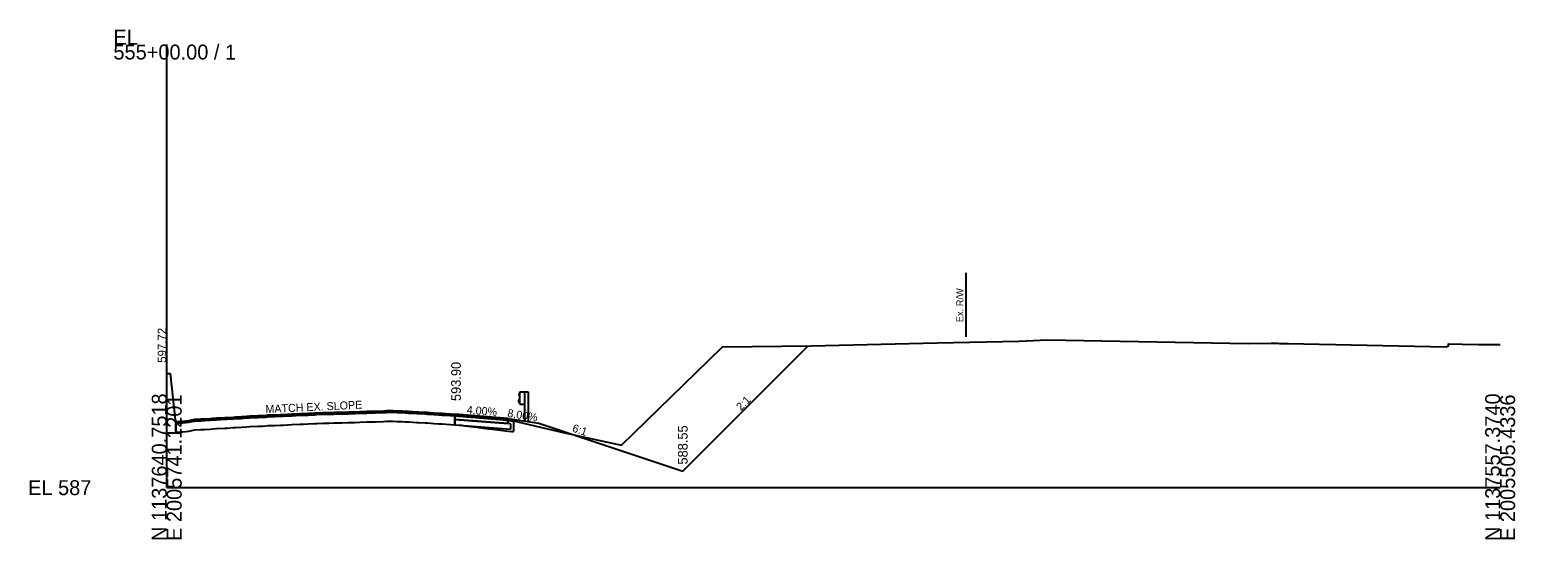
# Model space of a CAD drawing. Extents: x -201 to 2007062, y -213 to 1139737.
# Drawn here: x -25.7 to 252.8, y 8490.3 to 8585.9 of the extents above; entities that cross this region are included whole.
import ezdxf

# ---------------------------------------------------------------- set-up
doc = ezdxf.new("R2010")
doc.units = 0
for name, color, linetype in [('Default', 7, 'Continuous'), ('RD_GPK_XS_Cell', 7, 'Continuous'), ('RD_Sketch1', 7, 'Continuous'), ('RD_XS_Base', 7, 'Continuous'), ('RD_XS_EarthShd', 7, 'Continuous'), ('RD_XS_ExGround', 7, 'Continuous'), ('RD_XS_ExPaveRet', 7, 'Continuous'), ('RD_XS_ExRW', 7, 'Continuous'), ('RD_XS_GR', 7, 'Continuous'), ('RD_XS_PaveOvlay', 7, 'Continuous'), ('RD_XS_PaveShd', 7, 'Continuous'), ('RD_XS_TieSlope', 7, 'Continuous'), ('RD_XS_TX_Ditch', 7, 'Continuous'), ('RD_XS_TX_Elev_EX', 7, 'Continuous'), ('RD_XS_TX_Elev_PR', 7, 'Continuous'), ('RD_XS_TX_Slope', 7, 'Continuous')]:
    doc.layers.add(name, color=color, linetype=linetype)

msp = doc.modelspace()

# ---------------------------------------------------------------- linework, layer by layer
at = {"layer": 'RD_GPK_XS_Cell'}
for q in [(0, 8583.15), (250, 8500)]:
    msp.add_line((0, 8500), q, dxfattribs=at)
at = {"layer": 'RD_XS_Base'}
for points in [[(64, 8512.68), (54, 8513.48)], [(54, 8513.48), (54, 8512.82)], [(64.5, 8511.98), (64, 8512.02), (54, 8512.82)], [(54, 8512.82), (54, 8511.82)], [(54, 8512.82), (64, 8512.02)], [(64, 8512.02), (64, 8512.68)], [(64.5, 8510.98), (64.5, 8511.98)], [(54, 8511.82), (64.5, 8510.98)]]:
    msp.add_lwpolyline(points, dxfattribs=at)
at = {"layer": 'RD_XS_EarthShd'}
msp.add_lwpolyline([(64, 8513.01), (69.75, 8512.09)], dxfattribs=at)
at = {"layer": 'RD_XS_ExGround'}
msp.add_lwpolyline([(0, 8521.44), (0.65, 8521.43), (1.59, 8512.73), (1.68, 8512.41), (2.7, 8512.47), (3.03, 8512.49), (4.14, 8512.62), (4.73, 8512.75), (5.26, 8512.83), (6.41, 8512.89), (7.09, 8512.94), (8.11, 8512.99), (8.61, 8513.03), (9.3, 8513.09), (10.87, 8513.17), (11.25, 8513.19), (12.44, 8513.26), (12.86, 8513.28), (14, 8513.34), (14.98, 8513.41), (15.57, 8513.45), (17.14, 8513.52), (18.02, 8513.56), (18.59, 8513.6), (18.98, 8513.64), (19.83, 8513.66), (20.27, 8513.68), (21.34, 8513.73), (21.84, 8513.75), (23.46, 8513.84), (24.97, 8513.92), (25.58, 8513.94), (26.54, 8513.96), (27.71, 8514.03), (28.11, 8514.04), (29.24, 8514.11), (29.83, 8514.13), (30.4, 8514.11), (31.38, 8514.16), (31.81, 8514.16), (32.4, 8514.18), (32.81, 8514.19), (34.07, 8514.21), (34.38, 8514.22), (35.24, 8514.25), (36.19, 8514.29), (37.51, 8514.33), (38.31, 8514.35), (39.08, 8514.36), (40.64, 8514.41), (41.23, 8514.45), (42.46, 8514.5), (43.2, 8514.44), (43.54, 8514.43), (44.16, 8514.41), (44.68, 8514.38), (45.35, 8514.34), (46.91, 8514.26), (47.23, 8514.24), (48.48, 8514.18), (48.92, 8514.15), (50.05, 8514.06), (51.04, 8514), (51.61, 8513.96), (53.18, 8513.88), (55.29, 8513.7), (55.89, 8513.62), (58.16, 8513.34), (59.04, 8513.21), (59.41, 8513.16), (60.38, 8513.03), (61.02, 8512.99), (61.65, 8512.93), (62.58, 8512.82), (63.99, 8512.61), (64.62, 8512.54), (65, 8512.55), (74.34, 8510.36), (85.24, 8507.96), (101.65, 8523.92), (104.23, 8526.44), (120.84, 8526.63), (144.46, 8527.15), (159.8, 8527.52), (165.09, 8527.72), (202.77, 8527.04), (207.05, 8527.11), (207.55, 8527.1), (208.31, 8527.09), (208.61, 8527.08), (210.31, 8527.05), (216.04, 8526.93), (219.14, 8526.86), (239.91, 8526.43), (240.31, 8526.62), (240.34, 8526.97), (242.85, 8526.91), (245.93, 8526.86), (249.29, 8526.85), (250, 8526.85)], dxfattribs=at)
at = {"layer": 'RD_XS_ExPaveRet'}
for p, q in [((1.68, 8510.41), (1.68, 8512.41)), ((1.68, 8512.08), (1.68, 8510.41)), ((25.58, 8511.94), (26.54, 8511.96)), ((25.58, 8511.94), (26.54, 8511.96)), ((26.54, 8511.96), (27.71, 8512.03)), ((26.54, 8511.96), (27.71, 8512.03)), ((27.71, 8512.03), (28.11, 8512.04)), ((27.71, 8512.03), (28.11, 8512.04)), ((28.11, 8512.04), (29.24, 8512.11)), ((28.11, 8512.04), (29.24, 8512.11)), ((29.24, 8512.11), (29.83, 8512.13)), ((29.24, 8512.11), (29.83, 8512.13)), ((29.83, 8512.13), (30.4, 8512.11)), ((29.83, 8512.13), (30.4, 8512.11)), ((30.4, 8512.11), (31.38, 8512.16)), ((30.4, 8512.11), (31.38, 8512.16)), ((31.38, 8512.16), (31.81, 8512.16)), ((31.38, 8512.16), (31.81, 8512.16)), ((31.81, 8512.16), (32.4, 8512.18)), ((31.81, 8512.16), (32.4, 8512.18)), ((32.4, 8512.18), (32.81, 8512.19)), ((32.4, 8512.18), (32.81, 8512.19)), ((32.81, 8512.19), (34.07, 8512.21)), ((32.81, 8512.19), (34.07, 8512.21)), ((34.07, 8512.21), (34.38, 8512.22)), ((34.07, 8512.21), (34.38, 8512.22)), ((34.38, 8512.22), (35.24, 8512.25)), ((34.38, 8512.22), (35.24, 8512.25)), ((35.24, 8512.25), (36.19, 8512.29)), ((35.24, 8512.25), (36.19, 8512.29)), ((36.19, 8512.29), (37.51, 8512.33)), ((36.19, 8512.29), (37.51, 8512.33)), ((37.51, 8512.33), (38.31, 8512.35)), ((37.51, 8512.33), (38.31, 8512.35)), ((38.31, 8512.35), (39.08, 8512.36)), ((38.31, 8512.35), (39.08, 8512.36)), ((39.08, 8512.36), (40.64, 8512.41)), ((39.08, 8512.36), (40.64, 8512.41)), ((40.64, 8512.41), (41.23, 8512.45)), ((40.64, 8512.41), (41.23, 8512.45)), ((41.23, 8512.45), (42.46, 8512.5)), ((41.23, 8512.45), (42.46, 8512.5)), ((42.46, 8512.5), (43.2, 8512.44)), ((42.46, 8512.5), (43.2, 8512.44)), ((43.2, 8512.44), (43.54, 8512.43)), ((43.2, 8512.44), (43.54, 8512.43)), ((43.54, 8512.43), (44.16, 8512.41)), ((43.54, 8512.43), (44.16, 8512.41)), ((44.16, 8512.41), (44.68, 8512.38)), ((44.16, 8512.41), (44.68, 8512.38)), ((44.68, 8512.38), (45.35, 8512.34)), ((44.68, 8512.38), (45.35, 8512.34)), ((45.35, 8512.34), (46.91, 8512.26)), ((45.35, 8512.34), (46.91, 8512.26)), ((46.91, 8512.26), (47.23, 8512.24)), ((46.91, 8512.26), (47.23, 8512.24)), ((47.23, 8512.24), (48.48, 8512.18)), ((47.23, 8512.24), (48.48, 8512.18)), ((48.48, 8512.18), (48.92, 8512.15)), ((48.48, 8512.18), (48.92, 8512.15)), ((48.92, 8512.15), (50.05, 8512.06)), ((48.92, 8512.15), (50.05, 8512.06)), ((50.05, 8512.06), (51.04, 8512)), ((50.05, 8512.06), (51.04, 8512)), ((51.04, 8512), (51.61, 8511.96)), ((51.04, 8512), (51.61, 8511.96)), ((51.61, 8511.96), (53.18, 8511.88)), ((51.61, 8511.96), (53.18, 8511.88)), ((54, 8512.82), (54, 8513.48)), ((54, 8511.82), (54, 8512.82)), ((64.99, 8512.55), (64.99, 8510.55)), ((1.68, 8510.41), (2.7, 8510.47)), ((1.68, 8510.41), (2.7, 8510.47)), ((2.7, 8510.47), (3.03, 8510.49)), ((2.7, 8510.47), (3.03, 8510.49)), ((3.03, 8510.49), (4.14, 8510.62)), ((3.03, 8510.49), (4.14, 8510.62)), ((4.14, 8510.62), (4.73, 8510.75)), ((4.14, 8510.62), (4.73, 8510.75)), ((4.73, 8510.75), (5.26, 8510.83)), ((4.73, 8510.75), (5.26, 8510.83)), ((5.26, 8510.83), (6.41, 8510.89)), ((5.26, 8510.83), (6.41, 8510.89)), ((6.41, 8510.89), (7.09, 8510.94)), ((6.41, 8510.89), (7.09, 8510.94)), ((7.09, 8510.94), (8.11, 8510.99)), ((7.09, 8510.94), (8.11, 8510.99)), ((8.11, 8510.99), (8.61, 8511.03)), ((8.11, 8510.99), (8.61, 8511.03)), ((8.61, 8511.03), (9.3, 8511.09)), ((8.61, 8511.03), (9.3, 8511.09)), ((9.3, 8511.09), (10.87, 8511.17)), ((9.3, 8511.09), (10.87, 8511.17)), ((10.87, 8511.17), (11.25, 8511.19)), ((10.87, 8511.17), (11.25, 8511.19)), ((11.25, 8511.19), (12.44, 8511.26)), ((11.25, 8511.19), (12.44, 8511.26)), ((12.44, 8511.26), (12.86, 8511.28)), ((12.44, 8511.26), (12.86, 8511.28)), ((12.86, 8511.28), (14, 8511.34)), ((12.86, 8511.28), (14, 8511.34)), ((14, 8511.34), (14.98, 8511.41)), ((14, 8511.34), (14.98, 8511.41)), ((14.98, 8511.41), (15.57, 8511.45)), ((14.98, 8511.41), (15.57, 8511.45)), ((15.57, 8511.45), (17.14, 8511.52)), ((15.57, 8511.45), (17.14, 8511.52)), ((17.14, 8511.52), (18.02, 8511.56)), ((17.14, 8511.52), (18.02, 8511.56)), ((18.02, 8511.56), (18.59, 8511.6)), ((18.02, 8511.56), (18.59, 8511.6)), ((18.59, 8511.6), (18.98, 8511.64)), ((18.59, 8511.6), (18.98, 8511.64)), ((18.98, 8511.64), (19.83, 8511.66)), ((18.98, 8511.64), (19.83, 8511.66)), ((19.83, 8511.66), (20.27, 8511.68)), ((19.83, 8511.66), (20.27, 8511.68)), ((20.27, 8511.68), (21.34, 8511.73)), ((20.27, 8511.68), (21.34, 8511.73)), ((21.34, 8511.73), (21.84, 8511.75)), ((21.34, 8511.73), (21.84, 8511.75)), ((21.84, 8511.75), (23.46, 8511.84)), ((21.84, 8511.75), (23.46, 8511.84)), ((23.46, 8511.84), (24.97, 8511.92)), ((23.46, 8511.84), (24.97, 8511.92)), ((24.97, 8511.92), (25.58, 8511.94)), ((24.97, 8511.92), (25.58, 8511.94)), ((53.18, 8511.88), (55.29, 8511.7)), ((53.18, 8511.88), (54, 8511.81)), ((54, 8511.82), (54, 8511.81)), ((54, 8511.81), (54, 8511.82)), ((55.29, 8511.7), (55.89, 8511.62)), ((55.89, 8511.62), (58.16, 8511.34)), ((58.16, 8511.34), (59.04, 8511.21)), ((59.04, 8511.21), (59.41, 8511.16)), ((59.41, 8511.16), (60.38, 8511.03)), ((60.38, 8511.03), (61.02, 8510.99)), ((61.02, 8510.99), (61.65, 8510.93)), ((61.65, 8510.93), (62.58, 8510.82)), ((62.58, 8510.82), (63.99, 8510.61)), ((63.99, 8510.61), (64.62, 8510.54)), ((64.62, 8510.54), (64.99, 8510.55))]:
    msp.add_line(p, q, dxfattribs=at)
for points in [[(54, 8513.48), (53.18, 8513.55), (51.61, 8513.63), (51.04, 8513.66), (50.05, 8513.73), (48.92, 8513.81), (48.48, 8513.84), (47.23, 8513.91), (46.91, 8513.93), (45.35, 8514.01), (44.68, 8514.05), (44.16, 8514.08), (43.54, 8514.1), (43.2, 8514.11), (42.46, 8514.17), (41.23, 8514.11), (40.64, 8514.08), (39.08, 8514.03), (38.31, 8514.02), (37.51, 8514), (36.19, 8513.96), (35.24, 8513.92), (34.38, 8513.89), (34.07, 8513.88), (32.81, 8513.86), (32.4, 8513.85), (31.81, 8513.83), (31.38, 8513.82), (30.4, 8513.78), (29.83, 8513.8), (29.24, 8513.77), (28.11, 8513.71), (27.71, 8513.69), (26.54, 8513.63), (25.58, 8513.6), (24.97, 8513.59), (23.46, 8513.51), (21.84, 8513.42), (21.34, 8513.39), (20.27, 8513.35), (19.83, 8513.33), (18.98, 8513.3), (18.59, 8513.26), (18.02, 8513.23), (17.14, 8513.19), (15.57, 8513.12), (14.98, 8513.08), (14, 8513.01), (12.86, 8512.95), (12.44, 8512.93), (11.25, 8512.86), (10.87, 8512.84), (9.3, 8512.75), (8.61, 8512.7), (8.11, 8512.65), (7.09, 8512.61), (6.41, 8512.56), (5.26, 8512.49), (4.73, 8512.42), (4.14, 8512.29), (3.03, 8512.16), (2.7, 8512.14), (1.68, 8512.08)], [(1.68, 8512.08), (1.68, 8512.08)]]:
    msp.add_lwpolyline(points, dxfattribs=at)
at = {"layer": 'RD_XS_ExRW'}
msp.add_line((149.85, 8540.29), (149.85, 8528.29), dxfattribs=at)
at = {"layer": 'RD_XS_GR'}
for p, q in [((66.17, 8517.86), (66, 8517.46)), ((66.17, 8515.67), (66.17, 8518)), ((66.17, 8518), (67.08, 8518)), ((67.08, 8518), (67.08, 8512.51)), ((67.08, 8518), (67.75, 8518)), ((67.75, 8518), (67.75, 8512.4)), ((66, 8517.46), (66, 8517.36)), ((66, 8517.36), (66.17, 8516.96)), ((66, 8516.32), (66.17, 8516.72)), ((66, 8516.22), (66, 8516.32)), ((66.17, 8515.82), (66, 8516.22)), ((66.17, 8515.67), (67.08, 8515.67))]:
    msp.add_line(p, q, dxfattribs=at)
for centre, major_axis in [((66, 8512.69), (0, -0.02)), ((69.75, 8512.09), (0, -0.0204))]:
    msp.add_ellipse(centre, major_axis=major_axis, ratio=0.5, dxfattribs=at)
at = {"layer": 'RD_XS_PaveOvlay'}
for points in [[(1.68, 8512.41), (2.7, 8512.47), (3.03, 8512.49), (4.14, 8512.62), (4.73, 8512.75), (5.26, 8512.83), (6.41, 8512.89), (7.09, 8512.94), (8.11, 8512.99), (8.61, 8513.03), (9.3, 8513.09), (10.87, 8513.17), (11.25, 8513.19), (12.44, 8513.26), (12.86, 8513.28), (14, 8513.34), (14.98, 8513.41), (15.57, 8513.45), (17.14, 8513.52), (18.02, 8513.56), (18.59, 8513.6), (18.98, 8513.64), (19.83, 8513.66), (20.27, 8513.68), (21.34, 8513.73), (21.84, 8513.75), (23.46, 8513.84), (24.97, 8513.92), (25.58, 8513.94), (26.54, 8513.96), (27.71, 8514.03), (28.11, 8514.04), (29.24, 8514.11), (29.83, 8514.13), (30.4, 8514.11), (31.38, 8514.16), (31.81, 8514.16), (32.4, 8514.18), (32.81, 8514.19), (34.07, 8514.21), (34.38, 8514.22), (35.24, 8514.25), (36.19, 8514.29), (37.51, 8514.33), (38.31, 8514.35), (39.08, 8514.36), (40.64, 8514.41), (41.23, 8514.45), (42.46, 8514.5), (43.2, 8514.44), (43.54, 8514.43), (44.16, 8514.41), (44.68, 8514.38), (45.35, 8514.34), (46.91, 8514.26), (47.23, 8514.24), (48.48, 8514.18), (48.92, 8514.15), (50.05, 8514.06), (51.04, 8514), (51.61, 8513.96), (53.18, 8513.88), (54, 8513.81)], [(1.68, 8512.08), (2.7, 8512.14), (3.03, 8512.16), (4.14, 8512.29), (4.73, 8512.42), (5.26, 8512.49), (6.41, 8512.56), (7.09, 8512.61), (8.11, 8512.65), (8.61, 8512.7), (9.3, 8512.75), (10.87, 8512.84), (11.25, 8512.86), (12.44, 8512.93), (12.86, 8512.95), (14, 8513.01), (14.98, 8513.08), (15.57, 8513.12), (17.14, 8513.19), (18.02, 8513.23), (18.59, 8513.26), (18.98, 8513.3), (19.83, 8513.33), (20.27, 8513.35), (21.34, 8513.39), (21.84, 8513.42), (23.46, 8513.51), (24.97, 8513.59), (25.58, 8513.6), (26.54, 8513.63), (27.71, 8513.69), (28.11, 8513.71), (29.24, 8513.77), (29.83, 8513.8), (30.4, 8513.78), (31.38, 8513.82), (31.81, 8513.83), (32.4, 8513.85), (32.81, 8513.86), (34.07, 8513.88), (34.38, 8513.89), (35.24, 8513.92), (36.19, 8513.96), (37.51, 8514), (38.31, 8514.02), (39.08, 8514.03), (40.64, 8514.08), (41.23, 8514.11), (42.46, 8514.17), (43.2, 8514.11), (43.54, 8514.1), (44.16, 8514.08), (44.68, 8514.05), (45.35, 8514.01), (46.91, 8513.93), (47.23, 8513.91), (48.48, 8513.84), (48.92, 8513.81), (50.05, 8513.73), (51.04, 8513.66), (51.61, 8513.63), (53.18, 8513.55), (54, 8513.48)]]:
    msp.add_lwpolyline(points, dxfattribs=at)
at = {"layer": 'RD_XS_PaveShd'}
for points in [[(64, 8513.01), (54, 8513.81)], [(54, 8513.81), (54, 8513.48)], [(54, 8513.48), (64, 8512.68)], [(64, 8512.68), (64, 8513.01)]]:
    msp.add_lwpolyline(points, dxfattribs=at)
at = {"layer": 'RD_XS_TieSlope'}
msp.add_line((69.75, 8512.09), (96.75, 8503.09), dxfattribs=at)
msp.add_lwpolyline([(96.75, 8503.09), (120.28, 8526.62)], dxfattribs=at)

# ---------------------------------------------------------------- texts
at = {"layer": 'Default'}
msp.add_text('-', height=0.0001, dxfattribs=at).set_placement((0, 8500))
at = {"layer": 'RD_GPK_XS_Cell'}
for s, p in [('EL', (-10, 8583.15)), ('555+00.00 / 1', (-10, 8580.35)), ('EL 587', (-26, 8498.6))]:
    msp.add_text(s, height=2.8, dxfattribs=at).set_placement(p)
for s, p in [('N 1137640.7518', (0, 8490)), ('N 1137557.3740', (250, 8490)), ('E 2005741.1201', (2.8, 8490)), ('E 2005505.4336', (252.8, 8490))]:
    msp.add_text(s, height=2.8, rotation=90, dxfattribs=at).set_placement(p)
at = {"layer": 'RD_Sketch1'}
for s, p in [('Exterior Boundary', (115.4, 8526.53)), ('LOC_C', (115.73, 8526.53)), ('Exterior Boundary', (53.44, 8513.76)), ('EP_X_R', (53.73, 8513.76)), ('EP_X2', (53.79, 8512.77)), ('EP_X1', (53.8, 8513.43)), ('ESP1_R', (63.73, 8512.63)), ('ESP2_R', (63.73, 8511.97)), ('ESP_R', (63.77, 8512.96)), ('ESP4_R', (64.23, 8511.93)), ('ES_R', (65.82, 8512.64)), ('EP_X3', (53.79, 8511.77)), ('ESP3_R', (64.23, 8510.93))]:
    msp.add_text(s, height=0.05, dxfattribs=at).set_placement(p)
at = {"layer": 'RD_XS_ExRW'}
msp.add_text('Ex. R/W ', height=1.3, rotation=90, dxfattribs=at).set_placement((149.35, 8531.05))
at = {"layer": 'RD_XS_TX_Ditch'}
msp.add_text('588.55', height=1.8, rotation=90, dxfattribs=at).set_placement((97.65, 8504.33))
at = {"layer": 'RD_XS_TX_Elev_EX'}
msp.add_text('597.72', height=1.6, rotation=90, dxfattribs=at).set_placement((-0.1, 8523.44))
at = {"layer": 'RD_XS_TX_Elev_PR'}
msp.add_text('593.90', height=1.8, rotation=90, dxfattribs=at).set_placement((55.13, 8516.25))
at = {"layer": 'RD_XS_TX_Slope'}
for s, rotation, p in [('MATCH EX. SLOPE', 2.7318, (18.54, 8513.98)), ('4.00%', 355.4261, (56.2, 8513.89)), ('8.00%', 350.9097, (63.79, 8513.3)), ('2:1', 45, (107.66, 8514.35)), ('6:1', 341.5651, (75.91, 8510.56))]:
    msp.add_text(s, height=1.5, rotation=rotation, dxfattribs=at).set_placement(p)

doc.saveas('drawing.dxf')
